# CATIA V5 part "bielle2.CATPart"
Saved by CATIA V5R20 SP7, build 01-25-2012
Part number: bielle2
Publications: "droite_bielle_2", "droite-bielle_2.1", "droite_pivot_2_4", "droite_pivot_2_4_6", "droite_pivot_2_3"
Bounding box of the stored display mesh (mm): x -0.5 to 0, y 0.96 to 2.07, z 2.17 to 2.63
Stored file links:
  U:\IAO\bielle2.CATPart
  U:\IAO\skl_brevet_iao.CATProduct
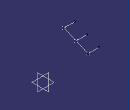
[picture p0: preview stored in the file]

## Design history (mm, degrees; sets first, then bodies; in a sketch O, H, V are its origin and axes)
Set1
  Point1 "point E": linked copy from another document
  Point2 "point B": linked copy from another document
  Point3 "point C": linked copy from another document
Set2
  Line1 "droite_bielle_2": type PtPt, FirstPoint Point1, SecondPoint Point2
  Line2 "droite-bielle_2.1": type PtPt, FirstPoint Point1, SecondPoint Point3
  Line3 "droite_pivot_2_4": type Normal, RefPoint Point1, RefSkin yz-plane, Start 0, End 0.5
  Line4 "droite_pivot_2_4_6": type Normal, RefPoint Point2, RefSkin yz-plane, Start 0, End 0.5
  Line5 "droite_pivot_2_3": type Normal, RefPoint Point3, RefSkin yz-plane, Start 0, End 0.5
Body1 (main body)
